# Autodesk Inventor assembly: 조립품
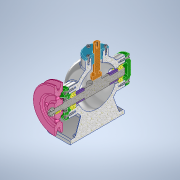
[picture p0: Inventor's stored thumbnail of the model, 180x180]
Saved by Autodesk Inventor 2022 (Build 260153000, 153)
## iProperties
Created: 2024-04
Part Number: 조립품
Document SubType Name: Assembly
Designer: Admin
Author: Admin
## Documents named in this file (16)
- C:\Users\Admin\Desktop\740406V1013\조립품.iam
- C:\Users\Admin\Desktop\740406V1013\본체.ipt
- C:\Users\Admin\Desktop\740406V1013\뒤커버.ipt
- C:\Users\Admin\Desktop\740406V1013\앞커버.ipt
- C:\Users\Admin\Desktop\740406V1013\상부커버.ipt
- C:\Users\Admin\Desktop\740406V1013\베어링- 6202.ipt
- KS B 2023 - 6202 - 15 x 35 x 11 - 7.8.ipt
- C:\Users\Admin\Desktop\740406V1013\칼라.ipt
- C:\Users\Admin\Desktop\740406V1013\편심축.ipt
- C:\Users\Admin\Desktop\740406V1013\키 4 x 4 x 12.ipt
- C:\Users\Admin\Desktop\740406V1013\오일실 15 30 7.ipt
- C:\Users\Admin\Desktop\740406V1013\V-벨트풀리.ipt
- C:\Users\Admin\Desktop\740406V1013\너트 M8.ipt
- C:\Users\Admin\Desktop\740406V1013\볼트 M4 x 16.ipt
- C:\Users\Admin\Desktop\740406V1013\볼트 M4 x 12.ipt
- C:\Users\Admin\Desktop\740406V1013\슬라이드.ipt
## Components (15 placed, 4 different names)
1. KS B 2023 - 6202 - 15 x 35 x 11 - 7.8:1
2. KS B 2023 - 6202 - 15 x 35 x 11 - 7.8:2
3. V-벨트풀리:1
4. ISO 4762 M4 x 16:1
5. ISO 4762 M4 x 16:2
6. ISO 4762 M4 x 16:3
7. ISO 4762 M4 x 16:4
8. ISO 4762 M4 x 16:5
9. ISO 4762 M4 x 16:6
10. ISO 4762 M4 x 16:7
11. ISO 4762 M4 x 16:8
12. KS B 1021 - 에 따름 ISO 1207 - 미터 A  M 4 x 12:1
13. KS B 1021 - 에 따름 ISO 1207 - 미터 A  M 4 x 12:2
14. KS B 1021 - 에 따름 ISO 1207 - 미터 A  M 4 x 12:3
15. KS B 1021 - 에 따름 ISO 1207 - 미터 A  M 4 x 12:4
